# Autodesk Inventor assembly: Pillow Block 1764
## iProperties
Created: 2009-01
Part Number: Pillow Block 1764
Document SubType Name: Assembly
Designer: lwoods
Mass: 25.286 g
Surface Area: 91.7026 cm^2
Volume: 18.0615 cm^3
Density: 1.4 g/cm^3
Author: lwoods
